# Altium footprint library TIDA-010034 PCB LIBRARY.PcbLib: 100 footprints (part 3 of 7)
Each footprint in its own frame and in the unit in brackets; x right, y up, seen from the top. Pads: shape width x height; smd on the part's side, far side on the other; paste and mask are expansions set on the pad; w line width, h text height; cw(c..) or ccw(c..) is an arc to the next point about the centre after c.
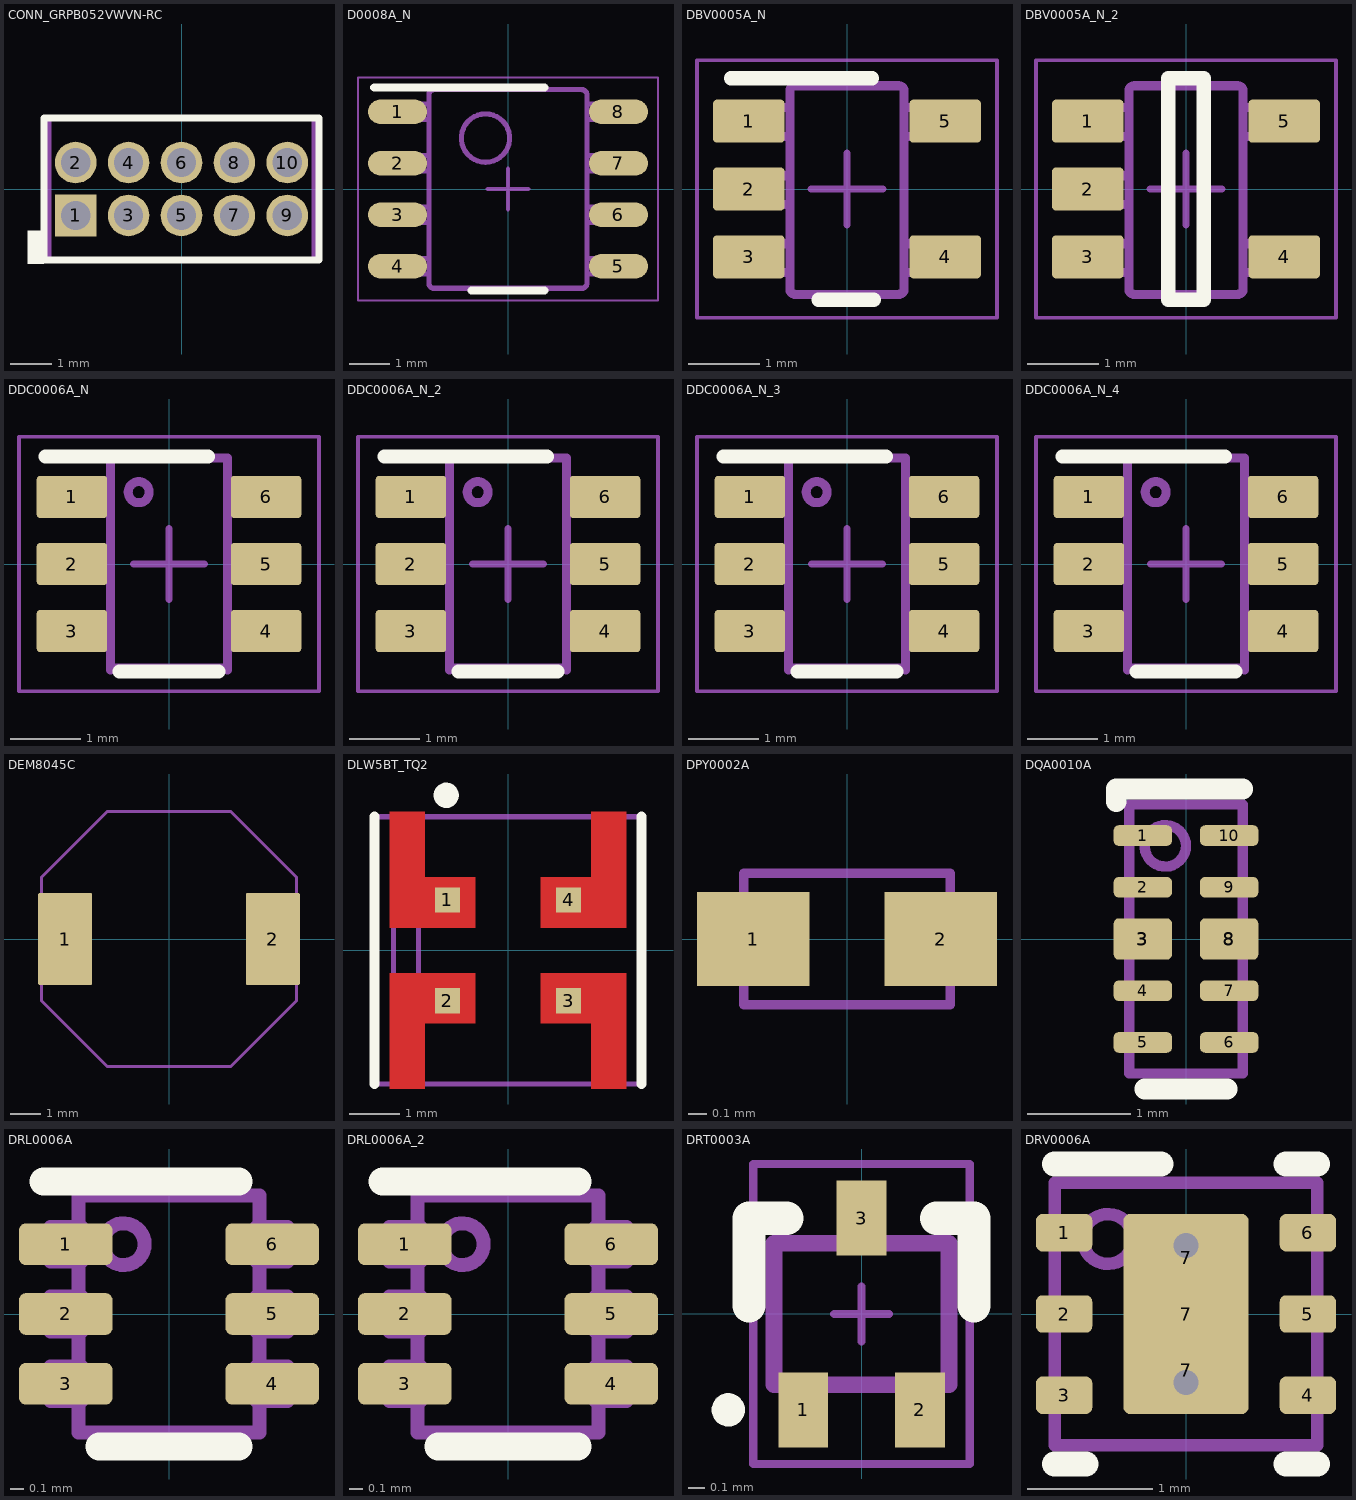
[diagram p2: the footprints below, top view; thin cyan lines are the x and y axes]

## CONN_GRPB052VWVN-RC [mm] "SULLINS"
height 4
pads (10):
  rect 1x1 hole 0.7 mask+0.08: 1(-2.54,-0.635)
  round 1 hole 0.7 mask+0.08: 2(-2.54,0.635) 3(-1.27,-0.635) 4(-1.27,0.635) 5(0,-0.635) 6(0,0.635) 7(1.27,-0.635) 8(1.27,0.635) 9(2.54,-0.635) 10(2.54,0.635)
Top Overlay:
  region: -3.3,-1.8 -3.3,-1 -3.7,-1 -3.7,-1.8
  lines w0.17: -3.3,-1.7 3.3,-1.7 3.3,1.7 -3.3,1.7 -3.3,0.6 -3.3,-1.7
Mechanical 5:
  lines w0.1: -3.175,-1.7 3.175,-1.7 3.175,1.7 -3.175,1.7 -3.175,-1.7
  text ".Designator" at -1.8,-0.5 h1
3D body: height 1, standoff 0, extent -3.174,-1.699 3.174,1.699
3D body: height 4, standoff -2.3, extent -1.469,-0.834 -1.071,-0.436
3D body: height 4, standoff -2.3, extent -2.739,0.436 -2.341,0.834
3D body: height 4, standoff -2.3, extent -1.469,0.436 -1.071,0.834
3D body: height 4, standoff -2.3, extent -0.199,-0.834 0.199,-0.436
3D body: height 4, standoff -2.3, extent 1.071,-0.834 1.469,-0.436
3D body: height 4, standoff -2.3, extent 2.341,-0.834 2.739,-0.436
3D body: height 4, standoff -2.3, extent -0.199,0.436 0.199,0.834
3D body: height 4, standoff -2.3, extent 1.071,0.436 1.469,0.834
3D body: height 4, standoff -2.3, extent 2.341,0.436 2.739,0.834
3D body: height 4, standoff -2.3, extent -2.739,-0.834 -2.34,-0.435

## D0008A_N [mm] "SOIC, 8-Leads, Body 4.9x3.9mm, Pitch 1.27mm, IPC Medium Density"
height 1.75
pads (8):
  oval 1.45x0.6 smd: 1(-2.725,1.905) 2(-2.725,0.635) 3(-2.725,-0.635) 4(-2.725,-1.905) 5(2.725,-1.905) 6(2.725,-0.635) 7(2.725,0.635) 8(2.725,1.905)
Top Overlay:
  lines w0.2: -3.3,2.5 0.9,2.5 ; -0.9,-2.5 0.9,-2.5
Mechanical 5:
  lines w0.127: -2.375,-2.095 -1.995,-2.095 -1.952,-2.095 -1.952,-1.715 -1.995,-1.715 -2.375,-1.715 ; -2.375,-2.095 -2.589,-2.095 -3.002,-2.095 -3.002,-1.715 -2.589,-1.715 -2.375,-1.715 ; -2.375,-2.095 -2.375,-1.715 ; -2.375,-0.825 -1.995,-0.825 -1.952,-0.825 -1.952,-0.445 -1.995,-0.445 -2.375,-0.445 ; -2.375,-0.825 -2.589,-0.825 -3.002,-0.825 -3.002,-0.445 -2.589,-0.445 -2.375,-0.445 ; -2.375,-0.825 -2.375,-0.445 ; -2.375,0.445 -1.995,0.445 -1.952,0.445 -1.952,0.825 -1.995,0.825 -2.375,0.825 ; -2.375,0.445 -2.589,0.445 -3.002,0.445 -3.002,0.825 -2.589,0.825 -2.375,0.825 ; -2.375,0.445 -2.375,0.825 ; -2.375,1.715 -1.995,1.715 -1.952,1.715 -1.952,2.095 -1.995,2.095 -2.375,2.095 ; -2.375,1.715 -2.589,1.715 -3.002,1.715 -3.002,2.095 -2.589,2.095 -2.375,2.095 ; -2.375,1.715 -2.375,2.095 ; -0.332,-2.45 -1.825,-2.45 -1.826,-2.45 cw(c-1.825,-2.323) -1.952,-2.324 -1.952,-2.323 -1.952,2.323 -1.952,2.324 cw(c-1.825,2.323) -1.826,2.45 -1.825,2.45 -0.332,2.45 ; -0.332,-2.45 -0.182,-2.45 ; -0.332,-2.45 -0.182,-2.45 ; -0.332,2.45 -0.182,2.45 ; -0.332,2.45 -0.182,2.45 ; -0.182,-2.45 0.178,-2.45 ; -0.182,2.45 0.178,2.45 ; 0.178,-2.45 0.328,-2.45 ; 0.178,-2.45 0.328,-2.45 ; 0.178,2.45 0.328,2.45 ; 0.178,2.45 0.328,2.45 ; 0.328,-2.45 1.821,-2.45 1.822,-2.45 ccw(c1.821,-2.323) 1.948,-2.324 1.948,-2.323 1.948,2.323 1.948,2.324 ccw(c1.821,2.323) 1.822,2.45 1.821,2.45 0.328,2.45 ; 2.371,-2.095 2.585,-2.095 2.998,-2.095 2.998,-1.715 2.585,-1.715 2.371,-1.715 ; 2.371,-2.095 1.991,-2.095 1.948,-2.095 1.948,-1.715 1.991,-1.715 2.371,-1.715 ; 2.371,-2.095 2.371,-1.715 ; 2.371,-0.825 2.585,-0.825 2.998,-0.825 2.998,-0.445 2.585,-0.445 2.371,-0.445 ; 2.371,-0.825 1.991,-0.825 1.948,-0.825 1.948,-0.445 1.991,-0.445 2.371,-0.445 ; 2.371,-0.825 2.371,-0.445 ; 2.371,0.445 2.585,0.445 2.998,0.445 2.998,0.825 2.585,0.825 2.371,0.825 ; 2.371,0.445 1.991,0.445 1.948,0.445 1.948,0.825 1.991,0.825 2.371,0.825 ; 2.371,0.445 2.371,0.825 ; 2.371,1.715 2.585,1.715 2.998,1.715 2.998,2.095 2.585,2.095 2.371,2.095 ; 2.371,1.715 1.991,1.715 1.948,1.715 1.948,2.095 1.991,2.095 2.371,2.095 ; 2.371,1.715 2.371,2.095 ; -0.555,0.659 cw(c-0.555,1.256) -0.555,1.853 cw(c-0.555,1.256) -0.555,0.659
  text ".Designator" at -1.625,-0.625 h0.89
Mechanical 15:
  lines w0.05: -3.7,-2.75 3.7,-2.75 3.7,2.75 -3.7,2.75 -3.7,-2.75
  lines w0.1: -0.5,0 0.5,0 ; 0,-0.5 0,0.5
3D body "D0008A.stp": height 1.63, standoff 0, extent -3,-2.45 3,2.45

## DBV0005A_N [mm] "SOT23, 5-Leads, Body 2.9x1.6mm, Pitch 0.95mm, Lead Span 2.8mm, IPC Medium Density"
height 1.45
pads (5):
  rrect17% 1x0.6 smd: 1(-1.375,0.95) 2(-1.375,0) 3(-1.375,-0.95) 4(1.375,-0.95) 5(1.375,0.95)
Top Overlay:
  lines w0.2: -1.625,1.55 0.35,1.55 ; -0.4,-1.55 0.375,-1.55
Mechanical 5:
  lines w0.127: -0.801,1.371 cw(c-0.725,1.37) -0.725,1.446 ; -0.801,1.37 -0.801,-1.399 -0.801,-1.4 ccw(c-0.725,-1.399) -0.725,-1.475 ; -0.801,1.37 -0.801,1.371 ; -0.725,-1.475 -0.725,-1.475 ; -0.725,-1.475 0.723,-1.475 0.724,-1.475 ccw(c0.723,-1.399) 0.799,-1.4 0.799,-1.399 0.799,1.37 ; -0.725,1.446 0.723,1.446 0.724,1.446 cw(c0.723,1.37) 0.799,1.371 ; -0.725,1.446 -0.725,1.446 ; 0.799,1.37 0.799,1.371 ; -1.423,-1.167 -1.199,-1.167 -1.105,-1.167 -1.088,-1.167 -0.835,-1.167 -0.801,-1.167 -0.801,-0.767 -0.835,-0.767 -1.088,-0.767 -1.105,-0.767 -1.199,-0.767 -1.423,-0.767 -1.423,-1.167 ; -1.423,-0.215 -1.199,-0.215 -1.105,-0.215 -1.088,-0.215 -0.835,-0.215 -0.801,-0.215 -0.801,0.186 -0.835,0.186 -1.088,0.186 -1.105,0.186 -1.199,0.186 -1.423,0.186 -1.423,-0.215 ; -1.423,0.738 -1.199,0.738 -1.105,0.738 -1.088,0.738 -0.835,0.738 -0.801,0.738 -0.801,1.138 -0.835,1.138 -1.088,1.138 -1.105,1.138 -1.199,1.138 -1.423,1.138 -1.423,0.738 ; 0.799,-1.167 0.799,-0.767 0.834,-0.767 1.087,-0.767 1.103,-0.767 1.198,-0.767 1.422,-0.767 1.422,-1.167 1.198,-1.167 1.103,-1.167 1.087,-1.167 0.834,-1.167 0.799,-1.167 ; 0.799,0.738 0.799,1.138 0.834,1.138 1.087,1.138 1.103,1.138 1.198,1.138 1.422,1.138 1.422,0.738 1.198,0.738 1.103,0.738 1.087,0.738 0.834,0.738 0.799,0.738
  text ".Designator" at -0.25,0.95 h0.51
Mechanical 15:
  lines w0.05: -2.1,-1.8 2.1,-1.8 2.1,1.8 -2.1,1.8 -2.1,-1.8
  lines w0.1: -0.5,0 0.5,0 ; 0,-0.5 0,0.5
3D body "DBV0005A.stp": height 1.09, standoff 0, extent -1.422,-1.461 1.423,1.46

## DBV0005A_N_2 [mm]
pads (5):
  rrect17% 1x0.6 smd: 1(-1.375,0.95) 2(-1.375,0) 3(-1.375,-0.95) 4(1.375,-0.95) 5(1.375,0.95)
Top Overlay:
  lines w0.2: -0.25,-1.55 0.25,-1.55 0.25,1.55 -0.25,1.55 -0.25,-1.55
Mechanical 5:
  lines w0.127: -0.801,1.371 cw(c-0.725,1.37) -0.725,1.446 ; -0.801,1.37 -0.801,-1.399 -0.801,-1.4 ccw(c-0.725,-1.399) -0.725,-1.475 ; -0.801,1.37 -0.801,1.371 ; -0.725,-1.475 -0.725,-1.475 ; -0.725,-1.475 0.723,-1.475 0.724,-1.475 ccw(c0.723,-1.399) 0.799,-1.4 0.799,-1.399 0.799,1.37 ; -0.725,1.446 0.723,1.446 0.724,1.446 cw(c0.723,1.37) 0.799,1.371 ; -0.725,1.446 -0.725,1.446 ; 0.799,1.37 0.799,1.371 ; -1.423,-1.167 -1.199,-1.167 -1.105,-1.167 -1.088,-1.167 -0.835,-1.167 -0.801,-1.167 -0.801,-0.767 -0.835,-0.767 -1.088,-0.767 -1.105,-0.767 -1.199,-0.767 -1.423,-0.767 -1.423,-1.167 ; -1.423,-0.215 -1.199,-0.215 -1.105,-0.215 -1.088,-0.215 -0.835,-0.215 -0.801,-0.215 -0.801,0.186 -0.835,0.186 -1.088,0.186 -1.105,0.186 -1.199,0.186 -1.423,0.186 -1.423,-0.215 ; -1.423,0.738 -1.199,0.738 -1.105,0.738 -1.088,0.738 -0.835,0.738 -0.801,0.738 -0.801,1.138 -0.835,1.138 -1.088,1.138 -1.105,1.138 -1.199,1.138 -1.423,1.138 -1.423,0.738 ; 0.799,-1.167 0.799,-0.767 0.834,-0.767 1.087,-0.767 1.103,-0.767 1.198,-0.767 1.422,-0.767 1.422,-1.167 1.198,-1.167 1.103,-1.167 1.087,-1.167 0.834,-1.167 0.799,-1.167 ; 0.799,0.738 0.799,1.138 0.834,1.138 1.087,1.138 1.103,1.138 1.198,1.138 1.422,1.138 1.422,0.738 1.198,0.738 1.103,0.738 1.087,0.738 0.834,0.738 0.799,0.738
  text ".Designator" at -0.25,0.95 h0.51
Mechanical 15:
  lines w0.05: -2.1,-1.8 2.1,-1.8 2.1,1.8 -2.1,1.8 -2.1,-1.8
  lines w0.1: -0.5,0 0.5,0 ; 0,-0.5 0,0.5
3D body "DBV0005A.stp": height 1.09, standoff 0, extent -1.422,-1.461 1.423,1.46

## DDC0006A_N [mm]
height 1.1
pads (6):
  rrect17% 1x0.6 smd: 1(-1.375,0.95) 2(-1.375,0) 3(-1.375,-0.95) 4(1.375,-0.95) 5(1.375,0) 6(1.375,0.95)
Top Overlay:
  lines w0.2: -1.75,1.525 0.55,1.525 ; -0.7,-1.524 0.7,-1.524
Mechanical 5:
  lines w0.127: -0.828,-1.5 -0.828,1.5 0.828,1.5 0.828,-1.5 ; -0.825,-1.165 -1.437,-1.165 -1.437,-0.735 -0.825,-0.735 ; -0.825,-0.215 -1.437,-0.215 -1.437,0.215 -0.825,0.215 ; -0.825,0.735 -1.437,0.735 -1.437,1.165 -0.825,1.165 ; -0.754,-1.47 -0.75,-1.47 0.743,-1.47 0.747,-1.47 ; -0.754,1.5 -0.75,1.5 ; 0.743,1.5 0.747,1.5 ; 0.825,-1.165 1.437,-1.165 1.437,-0.735 0.825,-0.735 ; 0.825,-0.215 1.437,-0.215 1.437,0.215 0.825,0.215 ; 0.825,0.735 1.437,0.735 1.437,1.165 0.825,1.165 ; -0.578,1.018 cw(c-0.43,1.018) -0.281,1.018 cw(c-0.43,1.018) -0.578,1.018
  text ".Designator" at -2.641,-0.246 h0.51
Mechanical 15:
  lines w0.05: -2.125,-1.8 2.125,-1.8 2.125,1.8 -2.125,1.8 -2.125,-1.8
  lines w0.1: -0.5,0 0.5,0 ; 0,-0.5 0,0.5
3D body "DDC0006A.stp": height 0.92, standoff 0, extent -1.434,-1.485 1.434,1.485

## DDC0006A_N_2 [mm]
pads (6):
  rrect17% 1x0.6 smd: 1(-1.375,0.95) 2(-1.375,0) 3(-1.375,-0.95) 4(1.375,-0.95) 5(1.375,0) 6(1.375,0.95)
Top Overlay:
  lines w0.2: -1.75,1.525 0.55,1.525 ; -0.7,-1.524 0.7,-1.524
Mechanical 5:
  lines w0.127: -0.828,-1.5 -0.828,1.5 0.828,1.5 0.828,-1.5 ; -0.825,-1.165 -1.437,-1.165 -1.437,-0.735 -0.825,-0.735 ; -0.825,-0.215 -1.437,-0.215 -1.437,0.215 -0.825,0.215 ; -0.825,0.735 -1.437,0.735 -1.437,1.165 -0.825,1.165 ; -0.754,-1.47 -0.75,-1.47 0.743,-1.47 0.747,-1.47 ; -0.754,1.5 -0.75,1.5 ; 0.743,1.5 0.747,1.5 ; 0.825,-1.165 1.437,-1.165 1.437,-0.735 0.825,-0.735 ; 0.825,-0.215 1.437,-0.215 1.437,0.215 0.825,0.215 ; 0.825,0.735 1.437,0.735 1.437,1.165 0.825,1.165 ; -0.578,1.018 cw(c-0.43,1.018) -0.281,1.018 cw(c-0.43,1.018) -0.578,1.018
  text ".Designator" at -0.246,2.641 h0.51
Mechanical 15:
  lines w0.05: -2.125,-1.8 2.125,-1.8 2.125,1.8 -2.125,1.8 -2.125,-1.8
  lines w0.1: -0.5,0 0.5,0 ; 0,-0.5 0,0.5
3D body "DDC0006A.stp": height 0.92, standoff 0, extent -1.434,-1.485 1.434,1.485

## DDC0006A_N_3 [mm]
pads (6):
  rrect17% 1x0.6 smd: 1(-1.375,0.95) 2(-1.375,0) 3(-1.375,-0.95) 4(1.375,-0.95) 5(1.375,0) 6(1.375,0.95)
Top Overlay:
  lines w0.2: -1.75,1.525 0.55,1.525 ; -0.7,-1.524 0.7,-1.524
Mechanical 5:
  lines w0.127: -0.828,-1.5 -0.828,1.5 0.828,1.5 0.828,-1.5 ; -0.825,-1.165 -1.437,-1.165 -1.437,-0.735 -0.825,-0.735 ; -0.825,-0.215 -1.437,-0.215 -1.437,0.215 -0.825,0.215 ; -0.825,0.735 -1.437,0.735 -1.437,1.165 -0.825,1.165 ; -0.754,-1.47 -0.75,-1.47 0.743,-1.47 0.747,-1.47 ; -0.754,1.5 -0.75,1.5 ; 0.743,1.5 0.747,1.5 ; 0.825,-1.165 1.437,-1.165 1.437,-0.735 0.825,-0.735 ; 0.825,-0.215 1.437,-0.215 1.437,0.215 0.825,0.215 ; 0.825,0.735 1.437,0.735 1.437,1.165 0.825,1.165 ; -0.578,1.018 cw(c-0.43,1.018) -0.281,1.018 cw(c-0.43,1.018) -0.578,1.018
  text ".Designator" at -0.246,2.641 h0.51
Mechanical 15:
  lines w0.05: -2.125,-1.8 2.125,-1.8 2.125,1.8 -2.125,1.8 -2.125,-1.8
  lines w0.1: -0.5,0 0.5,0 ; 0,-0.5 0,0.5
3D body "DDC0006A.stp": height 0.92, standoff 0, extent -1.434,-1.485 1.434,1.485

## DDC0006A_N_4 [mm]
pads (6):
  rrect17% 1x0.6 smd: 1(-1.375,0.95) 2(-1.375,0) 3(-1.375,-0.95) 4(1.375,-0.95) 5(1.375,0) 6(1.375,0.95)
Top Overlay:
  lines w0.2: -1.75,1.525 0.55,1.525 ; -0.7,-1.524 0.7,-1.524
Mechanical 5:
  lines w0.127: -0.828,-1.5 -0.828,1.5 0.828,1.5 0.828,-1.5 ; -0.825,-1.165 -1.437,-1.165 -1.437,-0.735 -0.825,-0.735 ; -0.825,-0.215 -1.437,-0.215 -1.437,0.215 -0.825,0.215 ; -0.825,0.735 -1.437,0.735 -1.437,1.165 -0.825,1.165 ; -0.754,-1.47 -0.75,-1.47 0.743,-1.47 0.747,-1.47 ; -0.754,1.5 -0.75,1.5 ; 0.743,1.5 0.747,1.5 ; 0.825,-1.165 1.437,-1.165 1.437,-0.735 0.825,-0.735 ; 0.825,-0.215 1.437,-0.215 1.437,0.215 0.825,0.215 ; 0.825,0.735 1.437,0.735 1.437,1.165 0.825,1.165 ; -0.578,1.018 cw(c-0.43,1.018) -0.281,1.018 cw(c-0.43,1.018) -0.578,1.018
  text ".Designator" at -0.246,2.641 h0.51
Mechanical 15:
  lines w0.05: -2.125,-1.8 2.125,-1.8 2.125,1.8 -2.125,1.8 -2.125,-1.8
  lines w0.1: -0.5,0 0.5,0 ; 0,-0.5 0,0.5
3D body "DDC0006A.stp": height 0.92, standoff 0, extent -1.434,-1.485 1.434,1.485

## DEM8045C [mm] "SMD, 2-Leads, Body 8x8mm, Pitch 6.75 mm"
height 4.5
pads (2):
  rrect6% 1.75x3 smd: 1(-3.375,0) 2(3.375,0)
Mechanical 5:
  lines w0.1: -4.15,-2 -2,-4.15 2,-4.15 4.15,-2 4.15,2 2,4.15 -2,4.15 -4.15,2 -4.15,-2
  text ".Designator" at 1.8,0.9 h1.02
3D body "DEM8045C.stp": height 4.5, standoff 0, extent -4.15,-4.15 4.15,4.15

## DLW5BT_TQ2 [mm] "SMD, 4-Leads, Body 5x5mm"
height 2.5
pads (4):
  rect 0.5x0.5 smd: 1(-1.2,1) 2(-1.2,-1) 3(1.2,-1) 4(1.2,1)
Top Layer:
  region: -2.35,-0.45 -0.65,-0.45 -0.65,-1.45 -1.65,-1.45 -1.65,-2.75 -2.35,-2.75
  region: -2.35,0.45 -0.65,0.45 -0.65,1.45 -1.65,1.45 -1.65,2.75 -2.35,2.75
  region: 2.35,-0.45 0.65,-0.45 0.65,-1.45 1.65,-1.45 1.65,-2.75 2.35,-2.75
  region: 2.35,0.45 0.65,0.45 0.65,1.45 1.65,1.45 1.65,2.75 2.35,2.75
Top Overlay:
  circle w0.25: c-1.225,3.075 r0.125
  lines w0.2: -2.65,-2.65 -2.65,2.65 ; 2.65,-2.65 2.65,2.65
Mechanical 5:
  lines w0.1: -2.65,-2.65 2.65,-2.65 2.65,2.65 -2.65,2.65 -2.65,-2.65 ; -2.275,-1.5 -2.275,1.5 -1.775,1.5 -1.775,-1.5 -2.275,-1.5
  text ".Designator" at -1.375,-0.475 h1.02
3D body: height 2.5, standoff 0, extent -2.65,-2.65 2.65,2.65
3D body: height 2.51, standoff 2.4, extent -2.275,-1.5 -1.775,1.5

## DPY0002A [mm] "R-PX2SON-N2"
height 0.4
pads (2):
  rect 0.6x0.5 smd: 1(-0.5,0) 2(0.5,0)
Mechanical 5:
  lines w0.05: -0.55,-0.35 0.55,-0.35 0.55,0.35 -0.55,0.35 -0.55,-0.35
  text ".Designator" at -0.475,-0.125 h0.25
3D body: height 0.4, standoff 0, extent -0.549,-0.349 0.549,0.349

## DQA0010A [mm] "SON, 10-Leads, Body 1x2.5mm, Pitch 0.5mm, TI Recommended"
height 0.55
pads (12):
  rrect50% 0.565x0.2 smd: 1(-0.417,1) 2(-0.417,0.5) 4(-0.417,-0.5) 5(-0.417,-1) 6(0.417,-1) 7(0.417,-0.5) 9(0.417,0.5) 10(0.417,1)
  rrect50% 0.565x0.36 on Top Paste: 3(-0.417,0) 8(0.417,0)
  rrect25% 0.565x0.4 smd paste-0.2: 3(-0.417,0) 8(0.417,0)
Top Overlay:
  lines w0.2: -0.675,1.33 -0.675,1.45 -0.55,1.45 0.55,1.45 ; -0.4,-1.45 0.4,-1.45
Mechanical 5:
  circle w0.1: c-0.2,0.9 r0.2
  lines w0.1: -0.55,-1.3 -0.55,1.3 0.55,1.3 0.55,-1.3 -0.55,-1.3
  text ".Designator" at -0.225,0.3 h0.38
3D body: height 0.55, standoff 0, extent -0.55,-1.3 0.55,1.3
3D body: height 0.56, standoff 0.3, extent -0.399,0.701 -0.001,1.099

## DRL0006A [mm] "SOTFL, 6-Flat Leads, Body 1.2x1.6x0.6mm, Pitch 0.5mm, TI recommended"
height 0.6
pads (6):
  rrect33% 0.67x0.3 smd: 1(-0.74,0.5) 2(-0.74,0) 3(-0.74,-0.5) 4(0.74,-0.5) 5(0.74,0) 6(0.74,0.5)
Top Overlay:
  lines w0.2: -0.9,0.95 0.5,0.95 ; -0.5,-0.95 0.5,-0.95
Mechanical 5:
  circle w0.1: c-0.325,0.5 r0.15
  lines w0.1: -0.65,-0.625 -0.65,-0.85 0.65,-0.85 0.65,-0.625 ; -0.65,-0.375 -0.65,-0.125 ; -0.65,0.125 -0.65,0.375 ; -0.65,0.625 -0.65,0.85 0.65,0.85 0.65,0.625 ; 0.65,-0.375 0.65,0.375 ; -0.85,-0.625 -0.85,-0.375 -0.627,-0.375 -0.627,-0.625 -0.85,-0.625 ; -0.85,-0.125 -0.627,-0.125 -0.627,0.125 -0.85,0.125 -0.85,-0.125 ; -0.85,0.375 -0.85,0.625 -0.627,0.625 -0.627,0.375 -0.85,0.375 ; 0.627,-0.625 0.627,-0.375 0.85,-0.375 0.85,-0.625 0.627,-0.625 ; 0.627,-0.125 0.85,-0.125 0.85,0.125 0.627,0.125 0.627,-0.125 ; 0.627,0.375 0.627,0.625 0.85,0.625 0.85,0.375 0.627,0.375
  text ".Designator" at -0.025,0.7 h0.65
3D body "DRL0006A.stp": height 0.61, standoff 0.01, extent -0.8,-0.8 0.8,0.8

## DRL0006A_2 [mm]
pads (6):
  rrect33% 0.67x0.3 smd: 1(-0.74,0.5) 2(-0.74,0) 3(-0.74,-0.5) 4(0.74,-0.5) 5(0.74,0) 6(0.74,0.5)
Top Overlay:
  lines w0.2: -0.9,0.95 0.5,0.95 ; -0.5,-0.95 0.5,-0.95
Mechanical 5:
  circle w0.1: c-0.325,0.5 r0.15
  lines w0.1: -0.65,-0.625 -0.65,-0.85 0.65,-0.85 0.65,-0.625 ; -0.65,-0.375 -0.65,-0.125 ; -0.65,0.125 -0.65,0.375 ; -0.65,0.625 -0.65,0.85 0.65,0.85 0.65,0.625 ; 0.65,-0.375 0.65,0.375 ; -0.85,-0.625 -0.85,-0.375 -0.627,-0.375 -0.627,-0.625 -0.85,-0.625 ; -0.85,-0.125 -0.627,-0.125 -0.627,0.125 -0.85,0.125 -0.85,-0.125 ; -0.85,0.375 -0.85,0.625 -0.627,0.625 -0.627,0.375 -0.85,0.375 ; 0.627,-0.625 0.627,-0.375 0.85,-0.375 0.85,-0.625 0.627,-0.625 ; 0.627,-0.125 0.85,-0.125 0.85,0.125 0.627,0.125 0.627,-0.125 ; 0.627,0.375 0.627,0.625 0.85,0.625 0.85,0.375 0.627,0.375
  text ".Designator" at -0.025,0.7 h0.65
3D body "DRL0006A.stp": height 0.61, standoff 0.01, extent -0.8,-0.8 0.8,0.8

## DRT0003A [mm] "SOTFL, 3-Leads, Body 1x1mm (inc leads), Pitch 0.35mm"
height 0.5
pads (3):
  rect 0.3x0.45 smd: 1(-0.35,-0.575) 2(0.35,-0.575) 3(0,0.575)
Top Overlay:
  circle w0.1: c-0.8,-0.575 r0.05
  lines w0.2: -0.675,0.05 -0.675,0.575 -0.45,0.575 ; 0.45,0.575 0.675,0.575 0.675,0.05
Mechanical 5:
  lines w0.1: -0.525,-0.425 -0.525,0.425 0.525,0.425 0.525,-0.425 -0.525,-0.425
  text ".Designator" at -0.381,-0.127 h0.2
Mechanical 15:
  lines w0.05: -0.165,0 0.165,0 ; 0,-0.165 0,0.165 ; -0.65,-0.9 0.65,-0.9 0.65,0.9 -0.65,0.9 -0.65,-0.9
3D body: height 0.5, standoff 0, extent -0.524,-0.424 0.524,0.424

## DRV0006A [mm] "SON, 6-Leads, Body 2x2mm, Pitch 0.65mm, Thermal Pad 1.6x1mm, TI Recommended"
height 0.8
pads (9):
  rrect33% 0.45x0.3 smd: 1(-0.975,0.65) 2(-0.975,0) 3(-0.975,-0.65) 4(0.975,-0.65) 5(0.975,0) 6(0.975,0.65)
  rrect50% 1x0.7 on Top Paste: 7(0,-0.45) 7(0,0.45)
  rrect10% 1x1.6 smd paste-0.5: 7(0,0)
via 0,0.55 diameter 0.5 hole 0.2
via 0,-0.55 diameter 0.5 hole 0.2
Top Overlay:
  lines w0.2: -1.05,-1.2 -0.8,-1.2 ; -1.05,1.2 -0.2,1.2 ; 0.8,-1.2 1.05,-1.2 ; 0.8,1.2 1.05,1.2
Mechanical 5:
  circle w0.1: c-0.625,0.6 r0.2
  lines w0.1: -1.05,-1.05 -1.05,1.05 1.05,1.05 1.05,-1.05 -1.05,-1.05
  text ".Designator" at -0.9,-0.5 h0.51
3D body: height 0.8, standoff 0, extent -1.05,-1.05 1.05,1.05
3D body: height 0.81, standoff 0.5, extent -0.824,0.401 -0.426,0.799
